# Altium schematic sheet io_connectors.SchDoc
size Tabloid; Organization: CMU Robotics Institute; Address1: Suite 780; Address2: 5001 Baum Blvd; Address3: Pittsburgh, PA 15213; Address4: USA
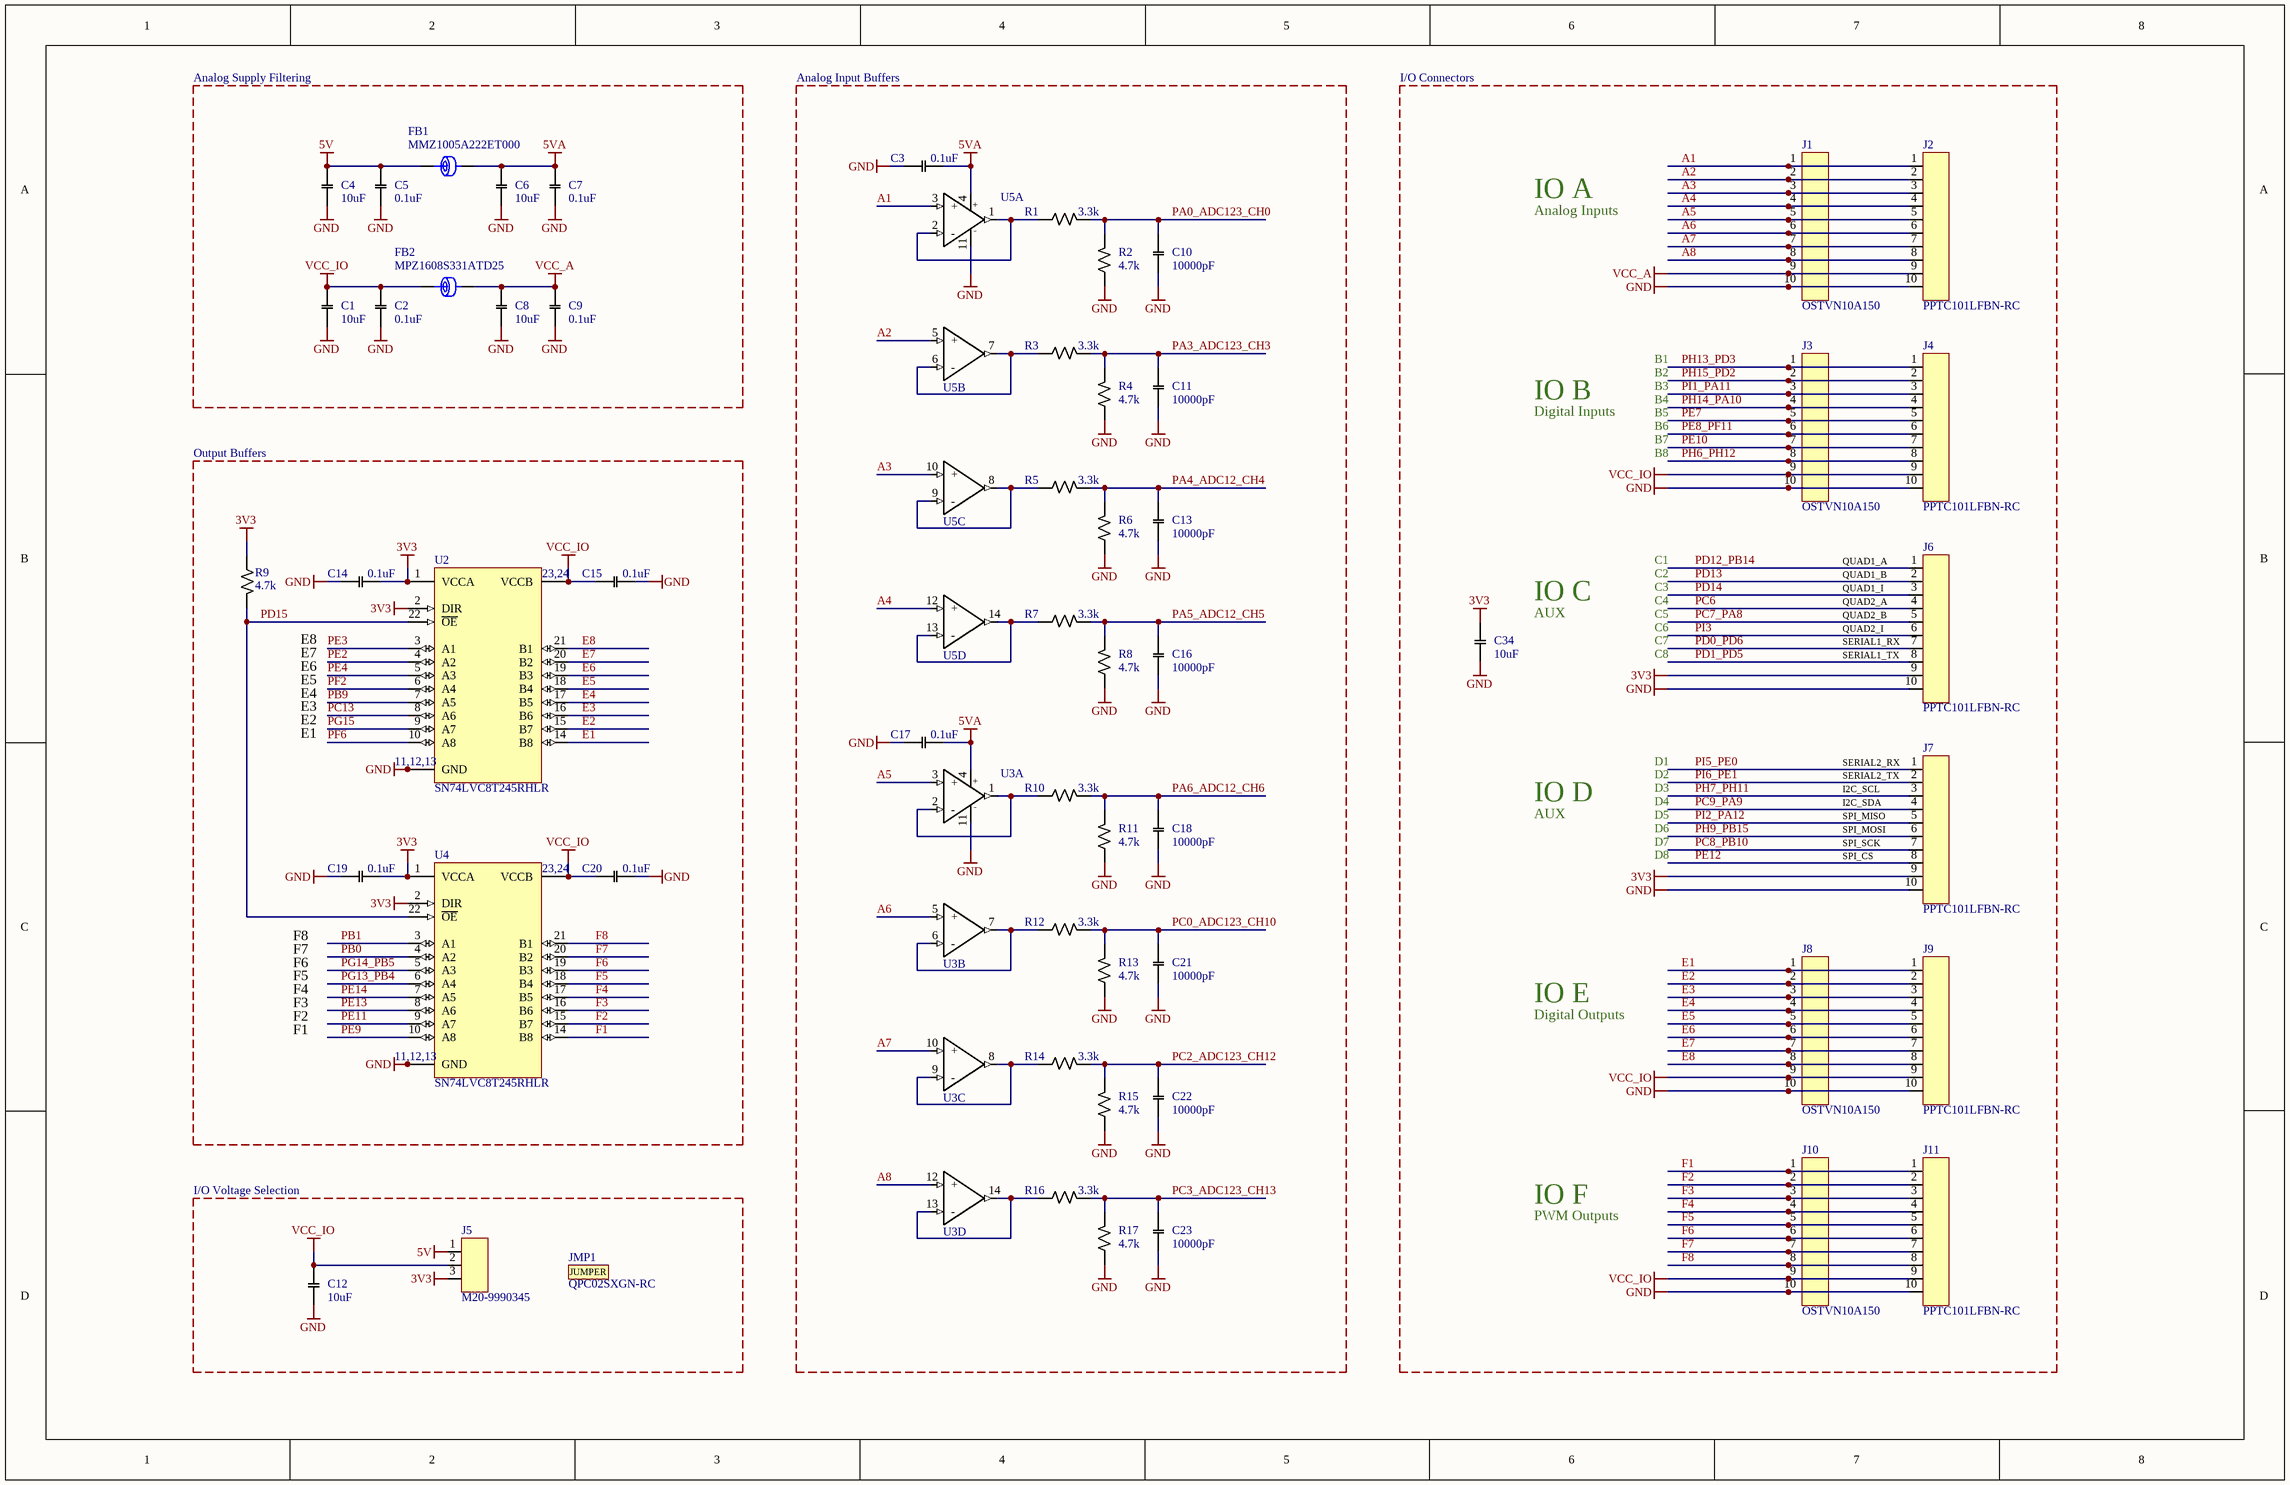
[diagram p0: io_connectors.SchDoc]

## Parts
C1  Capacitance: 10uF  [C0805]  (hidden comment: C-10uf-X5R-25V-10%-0805)
C2  Capacitance: 0.1uF  [C0402]  (hidden comment: C-0.1uf-X7R-25V-10%-0402)
C3  Capacitance: 0.1uF  [C0402]  (hidden comment: C-0.1uf-X7R-25V-10%-0402)
C4  Capacitance: 10uF  [C0805]  (hidden comment: C-10uf-X5R-25V-10%-0805)
C5  Capacitance: 0.1uF  [C0402]  (hidden comment: C-0.1uf-X7R-25V-10%-0402)
C6  Capacitance: 10uF  [C0805]  (hidden comment: C-10uf-X5R-25V-10%-0805)
C7  Capacitance: 0.1uF  [C0402]  (hidden comment: C-0.1uf-X7R-25V-10%-0402)
C8  Capacitance: 10uF  [C0805]  (hidden comment: C-10uf-X5R-25V-10%-0805)
C9  Capacitance: 0.1uF  [C0402]  (hidden comment: C-0.1uf-X7R-25V-10%-0402)
C10  Capacitance: 10000pF  [C0402]  (hidden comment: C-10000pf-X7R-50V-10%-0402)
C11  Capacitance: 10000pF  [C0402]  (hidden comment: C-10000pf-X7R-50V-10%-0402)
C12  Capacitance: 10uF  [C0805]  (hidden comment: C-10uf-X5R-25V-10%-0805)
C13  Capacitance: 10000pF  [C0402]  (hidden comment: C-10000pf-X7R-50V-10%-0402)
C14  Capacitance: 0.1uF  [C0402]  (hidden comment: C-0.1uf-X7R-25V-10%-0402)
C15  Capacitance: 0.1uF  [C0402]  (hidden comment: C-0.1uf-X7R-25V-10%-0402)
C16  Capacitance: 10000pF  [C0402]  (hidden comment: C-10000pf-X7R-50V-10%-0402)
C17  Capacitance: 0.1uF  [C0402]  (hidden comment: C-0.1uf-X7R-25V-10%-0402)
C18  Capacitance: 10000pF  [C0402]  (hidden comment: C-10000pf-X7R-50V-10%-0402)
C19  Capacitance: 0.1uF  [C0402]  (hidden comment: C-0.1uf-X7R-25V-10%-0402)
C20  Capacitance: 0.1uF  [C0402]  (hidden comment: C-0.1uf-X7R-25V-10%-0402)
C21  Capacitance: 10000pF  [C0402]  (hidden comment: C-10000pf-X7R-50V-10%-0402)
C22  Capacitance: 10000pF  [C0402]  (hidden comment: C-10000pf-X7R-50V-10%-0402)
C23  Capacitance: 10000pF  [C0402]  (hidden comment: C-10000pf-X7R-50V-10%-0402)
C34  Capacitance: 10uF  [C0805]  (hidden comment: C-10uf-X5R-25V-10%-0805)
FB1  MMZ1005A222ET000  [FB0402]
FB2  MPZ1608S331ATD25  [FB0603]
J1  OSTVN10A150  [OSTVN10A150]
J2  PPTC101LFBN-RC  [PPTC101LFBN-RC]
J3  OSTVN10A150  [OSTVN10A150]
J4  PPTC101LFBN-RC  [PPTC101LFBN-RC]
J5  M20-9990345  [M20-9990345]
J6  PPTC101LFBN-RC  [PPTC101LFBN-RC]
J7  PPTC101LFBN-RC  [PPTC101LFBN-RC]
J8  OSTVN10A150  [OSTVN10A150]
J9  PPTC101LFBN-RC  [PPTC101LFBN-RC]
J10  OSTVN10A150  [OSTVN10A150]
J11  PPTC101LFBN-RC  [PPTC101LFBN-RC]
JMP1  QPC02SXGN-RC  (mechanical)
R1  Resistance: 3.3k  [R0402]  (hidden comment: R-3.3k-0.1%-0.063w-0402)
R2  Resistance: 4.7k  [R0402]  (hidden comment: R-4.7k-0.1%-0.063w-0402)
R3  Resistance: 3.3k  [R0402]  (hidden comment: R-3.3k-0.1%-0.063w-0402)
R4  Resistance: 4.7k  [R0402]  (hidden comment: R-4.7k-0.1%-0.063w-0402)
R5  Resistance: 3.3k  [R0402]  (hidden comment: R-3.3k-0.1%-0.063w-0402)
R6  Resistance: 4.7k  [R0402]  (hidden comment: R-4.7k-0.1%-0.063w-0402)
R7  Resistance: 3.3k  [R0402]  (hidden comment: R-3.3k-0.1%-0.063w-0402)
R8  Resistance: 4.7k  [R0402]  (hidden comment: R-4.7k-0.1%-0.063w-0402)
R9  Resistance: 4.7k  [R0402]  (hidden comment: R-4.7k-1%-0.063w-0402)
R10  Resistance: 3.3k  [R0402]  (hidden comment: R-3.3k-0.1%-0.063w-0402)
R11  Resistance: 4.7k  [R0402]  (hidden comment: R-4.7k-0.1%-0.063w-0402)
R12  Resistance: 3.3k  [R0402]  (hidden comment: R-3.3k-0.1%-0.063w-0402)
R13  Resistance: 4.7k  [R0402]  (hidden comment: R-4.7k-0.1%-0.063w-0402)
R14  Resistance: 3.3k  [R0402]  (hidden comment: R-3.3k-0.1%-0.063w-0402)
R15  Resistance: 4.7k  [R0402]  (hidden comment: R-4.7k-0.1%-0.063w-0402)
R16  Resistance: 3.3k  [R0402]  (hidden comment: R-3.3k-0.1%-0.063w-0402)
R17  Resistance: 4.7k  [R0402]  (hidden comment: R-4.7k-0.1%-0.063w-0402)
U2  SN74LVC8T245RHLR  [R-PVQFN-N24_TI]
U3  TSV324IPT  [TSSOP14_ST]  (value not drawn)  (parts A,B,C,D of 4)
U4  SN74LVC8T245RHLR  [R-PVQFN-N24_TI]
U5  TSV324IPT  [TSSOP14_ST]  (value not drawn)  (parts A,B,C,D of 4)

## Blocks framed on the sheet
Analog Supply Filtering: C1 C2 C4-C9 FB1 FB2
Analog Input Buffers: C3 C10 C11 C13 C16-C18 C21-C23 R1-R8 R10-R17 U3 U5
I/O Voltage Selection: C12 J5 JMP1

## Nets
3V3: C14.2 C19.2 C34.2 J5.3 J6.9 J7.9 R9.1 U2.1(VCCA) U2.2(DIR) U4.1(VCCA) U4.2(DIR)
5V: C4.2 C5.1 FB1.1 J5.1
5VA: C3.1 C6.2 C7.1 C17.1 FB1.2 U3.4(V+) U5.4(V+)
GND: C1.1 C2.2 C3.2 C4.1 C5.2 C6.1 C7.2 C8.1 C9.1 C10.1 C11.1 C12.1 C13.1 C14.1 C15.1 C16.1 C17.2 C18.1 C19.1 C20.1 C21.1 C22.1 C23.1 C34.1 J1.10 J2.10 J3.10 J4.10 J6.10 J7.10 J8.10 J9.10 J10.10 J11.10 R2.1 R4.1 R6.1 R8.1 R11.1 R13.1 R15.1 R17.1 U2.11(GND) U2.12(GND) U2.13(GND) U3.11(V-) U4.11(GND) U4.12(GND) U4.13(GND) U5.11(V-)
VCC_A: C8.2 C9.2 FB2.2 J1.9 J2.9
VCC_IO: C1.2 C2.1 C12.2 C15.2 C20.2 FB2.1 J3.9 J4.9 J5.2 J8.9 J9.9 J10.9 J11.9 U2.23(VCCB) U2.24(VCCB) U4.23(VCCB) U4.24(VCCB)
A1: J1.1 J2.1 U5.3(+)
A2: J1.2 J2.2 U5.5(+)
A3: J1.3 J2.3 U5.10(+)
A4: J1.4 J2.4 U5.12(+)
A5: J1.5 J2.5 U3.3(+)
A6: J1.6 J2.6 U3.5(+)
A7: J1.7 J2.7 U3.10(+)
A8: J1.8 J2.8 U3.12(+)
E1: J8.1 J9.1 U2.14(B8)
E2: J8.2 J9.2 U2.15(B7)
E3: J8.3 J9.3 U2.16(B6)
E4: J8.4 J9.4 U2.17(B5)
E5: J8.5 J9.5 U2.18(B4)
E6: J8.6 J9.6 U2.19(B3)
E7: J8.7 J9.7 U2.20(B2)
E8: J8.8 J9.8 U2.21(B1)
F1: J10.1 J11.1 U4.14(B8)
F2: J10.2 J11.2 U4.15(B7)
F3: J10.3 J11.3 U4.16(B6)
F4: J10.4 J11.4 U4.17(B5)
F5: J10.5 J11.5 U4.18(B4)
F6: J10.6 J11.6 U4.19(B3)
F7: J10.7 J11.7 U4.20(B2)
F8: J10.8 J11.8 U4.21(B1)
PA0_ADC123_CH0: C10.2 R1.2 R2.2
PA3_ADC123_CH3: C11.2 R3.2 R4.2
PA4_ADC12_CH4: C13.2 R5.2 R6.2
PA5_ADC12_CH5: C16.2 R7.2 R8.2
PA6_ADC12_CH6: C18.2 R10.2 R11.2
PB0: U4.4(A2)
PB1: U4.3(A1)
PB9: U2.7(A5)
PC0_ADC123_CH10: C21.2 R12.2 R13.2
PC2_ADC123_CH12: C22.2 R14.2 R15.2
PC3_ADC123_CH13: C23.2 R16.2 R17.2
PC6: J6.4
PC7_PA8: J6.5
PC8_PB10: J7.7
PC9_PA9: J7.4
PC13: U2.8(A6)
PD0_PD6: J6.7
PD1_PD5: J6.8
PD12_PB14: J6.1
PD13: J6.2
PD14: J6.3
PD15: R9.2 U2.22(~{OE}) U4.22(~{OE})
PE2: U2.4(A2)
PE3: U2.3(A1)
PE4: U2.5(A3)
PE7: J3.5 J4.5
PE8_PF11: J3.6 J4.6
PE9: U4.10(A8)
PE10: J3.7 J4.7
PE11: U4.9(A7)
PE12: J7.8
PE13: U4.8(A6)
PE14: U4.7(A5)
PF2: U2.6(A4)
PF6: U2.10(A8)
PG13_PB4: U4.6(A4)
PG14_PB5: U4.5(A3)
PG15: U2.9(A7)
PH6_PH12: J3.8 J4.8
PH7_PH11: J7.3
PH9_PB15: J7.6
PH13_PD3: J3.1 J4.1
PH14_PA10: J3.4 J4.4
PH15_PD2: J3.2 J4.2
PI1_PA11: J3.3 J4.3
PI2_PA12: J7.5
PI3: J6.6
PI5_PE0: J7.1
PI6_PE1: J7.2
NetR1_1: R1.1 U5.1(OUT) U5.2(-)
NetR3_1: R3.1 U5.6(-) U5.7(OUT)
NetR5_1: R5.1 U5.8(OUT) U5.9(-)
NetR7_1: R7.1 U5.13(-) U5.14(OUT)
NetR10_1: R10.1 U3.1(OUT) U3.2(-)
NetR12_1: R12.1 U3.6(-) U3.7(OUT)
NetR14_1: R14.1 U3.8(OUT) U3.9(-)
NetR16_1: R16.1 U3.13(-) U3.14(OUT)

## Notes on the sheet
- I/O Connectors
- IO A
- Analog Inputs
- B1
- IO B
- Digital Inputs
- B2
- B3
- B4
- B5
- B6
- Output Buffers
- B7
- B8
- C1
- (near J6) QUAD1_A
- IO C
- AUX
- C2
- C3
- C4
- C5
- C6
- (near J6) QUAD1_B
- (near J6) QUAD1_I
- (near J6) QUAD2_A
- (near J6) QUAD2_B
- (near J6) QUAD2_I
- E4
- E5
- E6
- E7
- E8
- C7
- C8
- (near J6) SERIAL1_RX
- (near J6) SERIAL1_TX
- E1
- E2
- E3
- D1
- (near J7) SERIAL2_RX
- IO D
- D2
- D3
- D4
- D5
- D6
- (near J7) SPI_MISO
- (near J7) I2C_SCL
- (near J7) I2C_SDA
- (near J7) SERIAL2_TX
- (near J7) SPI_MOSI
- D7
- D8
- (near J7) SPI_SCK
- (near J7) SPI_CS
- F8
- F7
- F6
- F5
- F4
- F3
- F2
- F1
- IO E
- Digital Outputs
- IO F
- PWM Outputs

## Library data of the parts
C1 C4 C6 C8 C12 C34 = CMP-00042-6: Capacitor Ceramic 10uF 25V X5R 10% SMD 0805
C2 C3 C5 C7 C9 C14 C15 C17 C19 C20 = CMP-00040-11: Capacitor Ceramic 0.1uF 25V X7R 10% SMD 0402
C10 C11 C13 C16 C18 C21-C23 = CMP-00041-8: Capacitor Ceramic 10000pF 50V X7R 10% SMD 0402
FB1 = CMP-00233-4: FERRITE BEAD 2.2 KOHM 0402 1LN; Filter Type: Signal Line; Number of Lines: 1; Current Rating (Max): 150mA; DC Resistance (DCR) (Max): 2.2 Ohm
FB2 = CMP-00231-5: FERRITE CHIP 330 OHM 1.7A 0603; DC Resistance (DCR): 80 mOhm Max
J1 J3 J8 J10 = CMP-00332-3: CONN TERM BLOCK 2.54MM 10POS PCB; Manufacturer: On Shore Technology Inc.; Pitch: 0.100" (2.54mm); Number of Levels: 1; Positions Per Level: 10; Mating Orientation: Horizontal with Board; Current: 6A; Voltage: 125V; Wire Gauge: 20-30 AWG; Wire Termination: Screw - Rising Cage Clamp; Clamp Material - Plating: Brass; Screw Material - Plating: Steel - Zinc Plated; Torque - Screw: 0.15 Nm (1.3 Lb-In); Screw Thread: M1.6
J2 J4 J6 J7 J9 J11 = CMP-391-0001-1: CONN HEADER FEMALE 10POS.1" TIN; Manufacturer: Sullins Connector Solutions; Pitch: 0.100" (2.54mm); Number of Positions: 10; Number of Positions Loaded: All
J5 = CMP-00314-2: CONN HEADER VERT 3POS 2.54MM; Manufacturer: Harwin Inc.; Connector Type: Header, Unshrouded, Breakaway; Number of Positions: 3; Number of Positions Loaded: All; Pitch: 0.100" (2.54mm)
JMP1 = CMP-1305-000000-1: CONN JUMPER SHORTING .100" GOLD; Manufacturer: Sullins; Pitch: 0.1inch; Number of Positions: 2
R1 R3 R5 R7 R10 R12 R14 R16 = CMP-00138-3: Resistor 0402 3.3k Ohm 0.1% 1-16 Watt; Power: 0.063W, 1/16W
R2 R4 R6 R8 R11 R13 R15 R17 = CMP-00137-3: Resistor 0402 4.7k Ohm 0.1% 1-16 Watt; Power: 0.063W, 1/16W
R9 = CMP-00107-4: Resistor 0402 4.7k Ohm 1% 1-16 Watt; Power: 0.063W, 1/16W
U2 U4 = CMP-500-0004-4: IC BUS TRANSCVR 8BIT 24QFN; Data Rate: 500Mbps; Logic Function: Translator,Transceiver; Number of Bits: 8; Quiescent Current: 15uA; Min Supply Voltage: 1.65V; Max Supply Voltage: 5.5V; Propagation Delay: 4.3ns; Polarity: Non-Inverting; Direction: Bidirectional; Number of Elements: 1; Turn-On Delay Time: 4.2ns; Low Level Output Current: 32mA; High Level Output Current: -32mA
U3 U5 = CMP-736-0002-1: IC OPAMP GP 1.4MHZ RRO 14TSSOP; Manufacturer: STMicroelectronics; Amplifier Type: General Purpose; Current - Input Bias: 70nA; Current - Output / Channel: 80mA; Current - Supply: 500µA; Number of Circuits: 4; Output Type: Rail-to-Rail; Slew Rate: 0.6 V/µs; Voltage - Input Offset: 200µV; Voltage - Supply, Single/Dual (±): 2.5 V ~ 6 V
